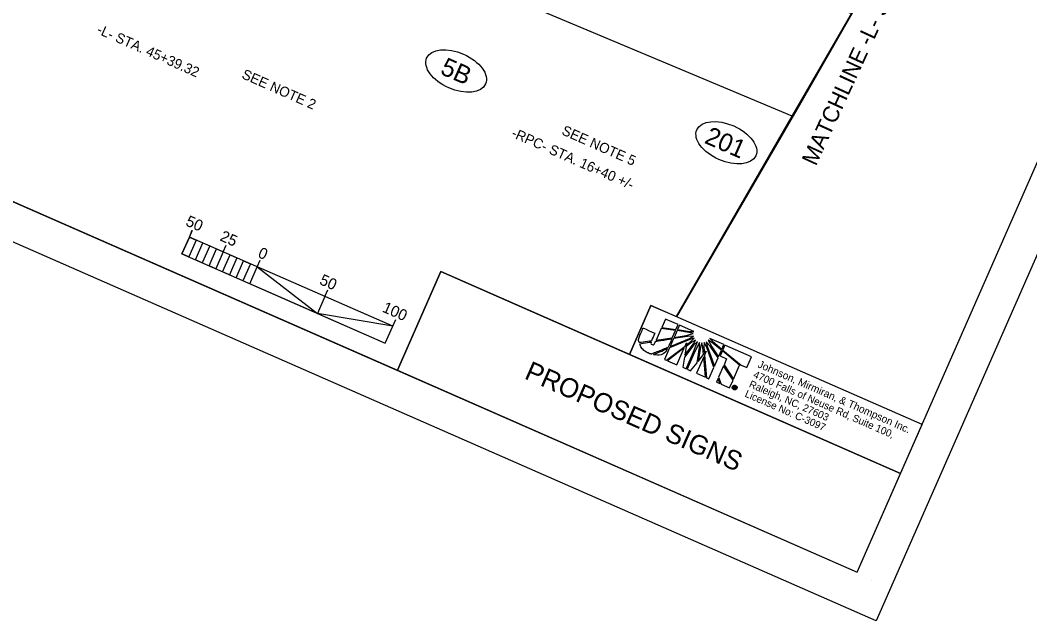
# Model space of a CAD drawing. Extents: x 1639021 to 1641149, y 842052 to 843739.
# Drawn here: x 1639988 to 1640670, y 842052 to 842458 of the extents above; entities that cross this region are included whole.
import ezdxf

# ---------------------------------------------------------------- set-up
doc = ezdxf.new("R2010")
doc.units = 0
for name, color, linetype in [('Default', 7, 'Continuous'), ('Prop Easement Permanent Drainage Utility', 7, 'Continuous'), ('Prop Easement Permanent Drainage Utility Station Offsets', 7, 'Continuous'), ('Prop Horizontal Alignment Tick Small', 7, 'Continuous'), ('Prop Parcel Number Text', 7, 'Continuous'), ('Prop ROW Marker CA CELL', 7, 'Continuous'), ('Prop ROW Marker CELL', 7, 'Continuous'), ('Prop ROW Text', 7, 'Continuous'), ('Prop Sign E Speed Limit XX CELL', 7, 'Continuous'), ('Scratch_Level_2', 7, 'Continuous')]:
    doc.layers.add(name, color=color, linetype=linetype)

msp = doc.modelspace()

# ---------------------------------------------------------------- linework, layer by layer
at = {"layer": 'Default'}
for p, q in [((1640424.27, 842256.42), (1640421.78, 842250.73)), ((1640432.85, 842252.67), (1640424.27, 842256.42)), ((1640431.4, 842249.36), (1640432.85, 842252.67)), ((1640433.76, 842252.32), (1640432.41, 842249.25)), ((1640443.41, 842248.09), (1640433.76, 842252.32)), ((1640421.5, 842250.08), (1640417.99, 842242.09)), ((1640431.13, 842248.73), (1640421.5, 842250.08)), ((1640421.78, 842250.73), (1640431.4, 842249.36)), ((1640428.95, 842243.77), (1640431.13, 842248.73)), ((1640432.12, 842248.58), (1640430.09, 842243.94)), ((1640430.09, 842243.94), (1640438.31, 842245.2)), ((1640440.18, 842247.41), (1640432.12, 842248.58)), ((1640432.41, 842249.25), (1640440.47, 842248.08)), ((1640438.31, 842245.2), (1640443.13, 842246.53)), ((1640443.25, 842244.89), (1640439.26, 842244.66)), ((1640443.13, 842246.53), (1640440.18, 842247.41)), ((1640440.47, 842248.08), (1640443.41, 842248.09)), ((1640440.58, 842243.29), (1640443.25, 842244.89)), ((1640417.99, 842242.09), (1640428.95, 842243.77)), ((1640425.03, 842228.54), (1640437.58, 842238.13)), ((1640440.74, 842242.66), (1640427.02, 842236.94)), ((1640427.42, 842237.84), (1640440.58, 842243.29)), ((1640429.76, 842243.19), (1640427.42, 842237.84)), ((1640439.26, 842244.66), (1640429.76, 842243.19)), ((1640443.56, 842238.88), (1640437.08, 842230.68)), ((1640437.32, 842231.99), (1640443.29, 842239.58)), ((1640437.58, 842238.13), (1640438.57, 842240.39)), ((1640442.03, 842240.68), (1640438.2, 842237.74)), ((1640438.31, 842238.65), (1640441.54, 842241.13)), ((1640438.57, 842240.39), (1640438.31, 842238.65)), ((1640443.79, 842243.42), (1640440.74, 842242.66)), ((1640441.54, 842241.13), (1640443.79, 842243.42)), ((1640444.69, 842242.12), (1640442.03, 842240.68)), ((1640443.29, 842239.58), (1640444.69, 842242.12)), ((1640443.34, 842234.19), (1640445.93, 842241.11)), ((1640445.93, 842241.11), (1640443.56, 842238.88)), ((1640447.35, 842240.49), (1640443.95, 842233.92)), ((1640447.28, 842237.25), (1640447.35, 842240.49)), ((1640448.89, 842240.27), (1640447.97, 842237.41)), ((1640449.59, 842237.37), (1640448.89, 842240.27)), ((1640450.44, 842240.51), (1640450.29, 842237.3)), ((1640451.95, 842237.75), (1640450.44, 842240.51)), ((1640451.9, 842241.1), (1640452.52, 842238.01)), ((1640454.48, 842237.99), (1640451.9, 842241.1)), ((1640452.52, 842238.01), (1640457.4, 842224.59)), ((1640453.23, 842242.1), (1640455.54, 842237.58)), ((1640455.73, 842240.6), (1640453.23, 842242.1)), ((1640463.82, 842239.1), (1640454.33, 842243.3)), ((1640454.33, 842243.3), (1640456.24, 842241.12)), ((1640459.8, 842230.08), (1640454.48, 842237.99)), ((1640462.18, 842235.36), (1640455.73, 842240.6)), ((1640456.24, 842241.12), (1640462.47, 842236.01)), ((1640462.47, 842236.01), (1640463.82, 842239.1)), ((1640464.5, 842238.85), (1640463.05, 842235.54)), ((1640482.53, 842230.95), (1640464.5, 842238.85)), ((1640427.02, 842236.94), (1640423.61, 842229.16)), ((1640437.04, 842236.9), (1640425.69, 842228.24)), ((1640432.09, 842225.44), (1640437.04, 842236.9)), ((1640438.2, 842237.74), (1640437.32, 842231.99)), ((1640438.33, 842222.76), (1640443.34, 842234.19)), ((1640443.95, 842233.92), (1640438.94, 842222.49)), ((1640445.62, 842226.77), (1640447.28, 842237.25)), ((1640447.97, 842237.41), (1640446.4, 842227.77)), ((1640446.4, 842227.77), (1640450.05, 842232.38)), ((1640450.05, 842232.38), (1640449.59, 842237.37)), ((1640450.29, 842237.3), (1640450.63, 842233.09)), ((1640450.63, 842233.09), (1640451.81, 842234.59)), ((1640451.81, 842234.59), (1640450.72, 842232.09)), ((1640450.72, 842232.09), (1640452.12, 842216.66)), ((1640457.01, 842223.7), (1640451.95, 842237.75)), ((1640455.54, 842237.58), (1640460.14, 842230.84)), ((1640460.14, 842230.84), (1640462.18, 842235.36)), ((1640462.76, 842234.87), (1640461.25, 842231.42)), ((1640461.25, 842231.42), (1640465.65, 842229.49)), ((1640462.79, 842234.93), (1640462.76, 842234.87)), ((1640474.41, 842225.31), (1640462.79, 842234.93)), ((1640463.05, 842235.54), (1640463.01, 842235.44)), ((1640463.01, 842235.44), (1640475.46, 842225.24)), ((1640423.61, 842229.16), (1640425.03, 842228.54)), ((1640425.69, 842228.24), (1640432.09, 842225.44)), ((1640437.08, 842230.68), (1640435.98, 842223.79)), ((1640441.32, 842221.45), (1640445.62, 842226.77)), ((1640450.18, 842230.86), (1640445.29, 842219.71)), ((1640451.43, 842217.02), (1640450.18, 842230.86)), ((1640457.4, 842224.59), (1640459.8, 842230.08)), ((1640463.54, 842224.67), (1640460.18, 842217)), ((1640469.97, 842215.18), (1640463.54, 842224.67)), ((1640465.65, 842229.49), (1640463.85, 842225.37)), ((1640463.85, 842225.37), (1640470.26, 842215.85)), ((1640470.26, 842215.85), (1640474.41, 842225.31)), ((1640475.46, 842225.24), (1640479.29, 842223.56)), ((1640479.29, 842223.56), (1640482.53, 842230.95)), ((1640435.98, 842223.79), (1640438.33, 842222.76)), ((1640438.94, 842222.49), (1640441.32, 842221.45)), ((1640445.29, 842219.71), (1640451.43, 842217.02)), ((1640453.64, 842216), (1640457.01, 842223.7)), ((1640452.12, 842216.66), (1640453.64, 842216)), ((1640459.81, 842216.16), (1640458.76, 842213.76)), ((1640458.76, 842213.76), (1640460.98, 842212.78)), ((1640460.98, 842212.78), (1640459.81, 842216.16)), ((1640460.18, 842217), (1640461.83, 842212.41)), ((1640461.83, 842212.41), (1640467.64, 842209.86)), ((1640467.64, 842209.86), (1640469.97, 842215.18)), ((1640470.26, 842209.68), (1640470.83, 842210.99)), ((1640470.83, 842210.99), (1640471.37, 842210.76)), ((1640471.37, 842210.76), (1640471.26, 842210.51)), ((1640471.26, 842210.51), (1640471.37, 842210.76)), ((1640471.37, 842210.76), (1640471.45, 842210.72)), ((1640471.7, 842211.53), (1640471.58, 842211.26)), ((1640471.58, 842211.26), (1640471.7, 842211.53)), ((1640470.55, 842209.55), (1640470.26, 842209.68)), ((1640470.57, 842208.94), (1640470.44, 842208.65)), ((1640470.44, 842208.65), (1640470.57, 842208.94)), ((1640470.45, 842208.65), (1640470.44, 842208.65)), ((1640470.78, 842210.07), (1640470.55, 842209.55)), ((1640470.57, 842208.94), (1640470.58, 842208.93)), ((1640471.02, 842209.96), (1640470.78, 842210.07)), ((1640471.02, 842210.61), (1640470.88, 842210.3)), ((1640470.88, 842210.3), (1640471.12, 842210.2)), ((1640471.26, 842210.51), (1640471.02, 842210.61)), ((1640471.12, 842210.2), (1640471.02, 842209.96)), ((1640471.02, 842209.96), (1640471.12, 842210.2)), ((1640471.03, 842209.96), (1640471.02, 842209.96)), ((1640471.12, 842210.2), (1640471.13, 842210.19)), ((1640471.29, 842210.49), (1640471.26, 842210.51))]:
    msp.add_line(p, q, dxfattribs=at)
msp.add_lwpolyline([(1640399.95, 842232.52), (1640583.09, 842152.07), (1640597.61, 842185.12), (1640414.46, 842265.57)], close=True, dxfattribs=at)
for points in [[(1640421.78, 842250.73), (1640431.4, 842249.36), (1640432.85, 842252.67), (1640424.27, 842256.42), (1640421.78, 842250.73)], [(1640440.47, 842248.08), (1640443.41, 842248.09), (1640433.76, 842252.32), (1640432.41, 842249.25), (1640440.47, 842248.08)], [(1640417.99, 842242.09), (1640428.95, 842243.77), (1640431.13, 842248.73), (1640421.5, 842250.08), (1640417.99, 842242.09)], [(1640429.76, 842243.19), (1640427.42, 842237.84), (1640440.58, 842243.29), (1640443.25, 842244.89), (1640439.26, 842244.66), (1640429.76, 842243.19)], [(1640432.12, 842248.58), (1640430.09, 842243.94), (1640438.31, 842245.2), (1640443.13, 842246.53), (1640440.18, 842247.41), (1640432.12, 842248.58)], [(1640443.79, 842243.42), (1640440.74, 842242.66), (1640427.02, 842236.94), (1640423.61, 842229.16), (1640425.03, 842228.54), (1640437.58, 842238.13), (1640438.57, 842240.39), (1640438.31, 842238.65), (1640441.54, 842241.13), (1640443.79, 842243.42)], [(1640443.56, 842238.88), (1640437.08, 842230.68), (1640435.98, 842223.79), (1640438.33, 842222.76), (1640443.34, 842234.19), (1640445.93, 842241.11), (1640443.56, 842238.88)], [(1640444.69, 842242.12), (1640442.03, 842240.68), (1640438.2, 842237.74), (1640437.32, 842231.99), (1640443.29, 842239.58), (1640444.69, 842242.12)], [(1640447.35, 842240.49), (1640443.95, 842233.92), (1640438.94, 842222.49), (1640441.32, 842221.45), (1640445.62, 842226.77), (1640447.28, 842237.25), (1640447.35, 842240.49)], [(1640448.89, 842240.27), (1640447.97, 842237.41), (1640446.4, 842227.77), (1640450.05, 842232.38), (1640449.59, 842237.37), (1640448.89, 842240.27)], [(1640450.44, 842240.51), (1640450.29, 842237.3), (1640450.63, 842233.09), (1640451.81, 842234.59), (1640450.72, 842232.09), (1640452.12, 842216.66), (1640453.64, 842216), (1640457.01, 842223.7), (1640451.95, 842237.75), (1640450.44, 842240.51)], [(1640451.9, 842241.1), (1640452.52, 842238.01), (1640457.4, 842224.59), (1640459.8, 842230.08), (1640454.48, 842237.99), (1640451.9, 842241.1)], [(1640453.23, 842242.1), (1640455.54, 842237.58), (1640460.14, 842230.84), (1640462.18, 842235.36), (1640455.73, 842240.6), (1640453.23, 842242.1)], [(1640456.24, 842241.12), (1640462.47, 842236.01), (1640463.82, 842239.1), (1640454.33, 842243.3), (1640456.24, 842241.12)], [(1640482.53, 842230.95), (1640464.5, 842238.85), (1640463.05, 842235.54), (1640463.01, 842235.44), (1640475.46, 842225.24), (1640479.29, 842223.56), (1640482.53, 842230.95)], [(1640425.69, 842228.24), (1640432.09, 842225.44), (1640437.04, 842236.9), (1640425.69, 842228.24)], [(1640462.79, 842234.93), (1640462.76, 842234.87), (1640461.25, 842231.42), (1640465.65, 842229.49), (1640463.85, 842225.37), (1640470.26, 842215.85), (1640474.41, 842225.31), (1640462.79, 842234.93)], [(1640445.29, 842219.71), (1640451.43, 842217.02), (1640450.18, 842230.86), (1640445.29, 842219.71)], [(1640463.54, 842224.67), (1640460.18, 842217), (1640461.83, 842212.41), (1640467.64, 842209.86), (1640469.97, 842215.18), (1640463.54, 842224.67), (1640463.54, 842224.67)], [(1640458.76, 842213.76), (1640458.76, 842213.76), (1640460.98, 842212.78), (1640459.81, 842216.16), (1640458.76, 842213.76)], [(1640471.5, 842209.51), (1640471.47, 842209.44), (1640471.46, 842209.38), (1640471.44, 842209.34), (1640471.41, 842209.18), (1640471.14, 842209.3)]]:
    msp.add_lwpolyline(points, dxfattribs=at)
for points, degree in [([(1640417.14, 842246.85), (1640417.14, 842246.85), (1640409.21, 842250.33), (1640409.21, 842250.33), (1640409.21, 842250.33), (1640407.03, 842245.36), (1640407.03, 842245.36), (1640407.03, 842245.36), (1640406.8, 842244.84), (1640406.8, 842244.84), (1640406.12, 842243.28), (1640406.09, 842241.82), (1640406.54, 842240.4), (1640406.54, 842240.4), (1640414.8, 842241.5), (1640414.84, 842241.6), (1640414.84, 842241.6), (1640417.14, 842246.85), (1640417.14, 842246.85)], 3), ([(1640415.24, 842239.16), (1640414.74, 842239.39), (1640414.42, 842239.86), (1640414.65, 842240.89), (1640414.65, 842240.89), (1640406.83, 842239.78), (1640406.83, 842239.78), (1640407.85, 842236.95), (1640410.36, 842234.44), (1640412.92, 842233.32), (1640413.59, 842233.03), (1640414.12, 842232.86), (1640414.89, 842232.69), (1640414.89, 842232.69), (1640426.11, 842237.29), (1640426.11, 842237.29), (1640426.11, 842237.29), (1640428.64, 842243.06), (1640428.64, 842243.06), (1640428.64, 842243.06), (1640417.68, 842241.37), (1640417.68, 842241.37), (1640416.73, 842239.2), (1640415.95, 842238.85), (1640415.24, 842239.16)], 3), ([(1640415.24, 842239.16), (1640414.74, 842239.39), (1640414.42, 842239.86), (1640414.65, 842240.89), (1640414.65, 842240.89), (1640406.83, 842239.78), (1640406.83, 842239.78), (1640407.85, 842236.95), (1640410.36, 842234.44), (1640412.92, 842233.32), (1640413.59, 842233.03), (1640414.12, 842232.86), (1640414.89, 842232.69), (1640414.89, 842232.69), (1640426.11, 842237.29), (1640426.11, 842237.29), (1640426.11, 842237.29), (1640428.64, 842243.06), (1640428.64, 842243.06), (1640428.64, 842243.06), (1640417.68, 842241.37), (1640417.68, 842241.37), (1640416.73, 842239.2), (1640415.95, 842238.85), (1640415.24, 842239.16)], 3), ([(1640425.71, 842236.38), (1640425.71, 842236.38), (1640416.02, 842232.42), (1640416.02, 842232.42), (1640419.64, 842231.79), (1640423.84, 842232.53), (1640425.71, 842236.38)], 3), ([(1640470.44, 842208.65), (1640470.05, 842208.82), (1640469.77, 842209.12), (1640469.6, 842209.53), (1640469.44, 842209.93), (1640469.45, 842210.34), (1640469.62, 842210.74), (1640469.8, 842211.15), (1640470.1, 842211.43), (1640470.5, 842211.57), (1640470.9, 842211.71), (1640471.3, 842211.71), (1640471.7, 842211.53)], 3), ([(1640471.58, 842211.26), (1640471.26, 842211.4), (1640470.94, 842211.41), (1640470.62, 842211.3), (1640470.3, 842211.17), (1640470.05, 842210.94), (1640469.91, 842210.62), (1640469.77, 842210.29), (1640469.76, 842209.96), (1640469.89, 842209.63), (1640470.02, 842209.3), (1640470.25, 842209.08), (1640470.57, 842208.94)], 3), ([(1640470.58, 842208.93), (1640470.9, 842208.79), (1640471.22, 842208.78), (1640471.55, 842208.9), (1640471.87, 842209.03), (1640472.12, 842209.27), (1640472.26, 842209.59), (1640472.4, 842209.91), (1640472.41, 842210.25), (1640472.28, 842210.57), (1640472.15, 842210.89), (1640471.92, 842211.11), (1640471.58, 842211.26)], 3), ([(1640471.45, 842210.72), (1640471.78, 842210.58), (1640471.89, 842210.37), (1640471.78, 842210.11), (1640471.72, 842209.99), (1640471.64, 842209.92), (1640471.5, 842209.89)], 3), ([(1640471.7, 842211.53), (1640472.11, 842211.36), (1640472.39, 842211.06), (1640472.56, 842210.66), (1640472.73, 842210.28), (1640472.72, 842209.87), (1640472.54, 842209.46)], 3), ([(1640472.54, 842209.46), (1640472.37, 842209.06), (1640472.07, 842208.77), (1640471.67, 842208.61), (1640471.27, 842208.46), (1640470.86, 842208.47), (1640470.45, 842208.65)], 3), ([(1640471.23, 842209.81), (1640471.21, 842209.85), (1640471.15, 842209.9), (1640471.03, 842209.96)], 2), ([(1640471.13, 842210.19), (1640471.32, 842210.11), (1640471.44, 842210.13), (1640471.49, 842210.24), (1640471.53, 842210.33), (1640471.47, 842210.42), (1640471.29, 842210.49)], 3), ([(1640471.14, 842209.3), (1640471.13, 842209.38), (1640471.14, 842209.47), (1640471.18, 842209.56), (1640471.23, 842209.68), (1640471.25, 842209.76), (1640471.23, 842209.81)], 3), ([(1640471.5, 842209.89), (1640471.56, 842209.81), (1640471.56, 842209.68), (1640471.5, 842209.51)], 2)]:
    msp.add_open_spline(points, degree=degree, dxfattribs=at)
at = {"layer": 'Prop Easement Permanent Drainage Utility Station Offsets'}
for p, q in [((1640102.72, 842311.83), (1640104.72, 842316.4)), ((1640102.72, 842311.83), (1640097.69, 842300.39)), ((1640240.06, 842251.52), (1640102.72, 842311.83)), ((1640125.6, 842301.77), (1640127.62, 842306.36)), ((1640097.69, 842300.39), (1640235.02, 842240.06)), ((1640134.76, 842297.76), (1640129.74, 842286.31)), ((1640148.49, 842291.72), (1640150.5, 842296.29)), ((1640194.28, 842271.62), (1640196.28, 842276.19)), ((1640194.28, 842271.62), (1640189.25, 842260.18)), ((1640240.06, 842251.52), (1640242.07, 842256.09)), ((1640235.02, 842240.06), (1640240.06, 842251.52))]:
    msp.add_line(p, q, dxfattribs=at)
for points in [[(1640102.72, 842311.83), (1640107.3, 842309.82), (1640102.27, 842298.38), (1640097.69, 842300.39)], [(1640111.87, 842307.81), (1640116.45, 842305.79), (1640111.42, 842294.35), (1640106.85, 842296.35)], [(1640121.02, 842303.78), (1640125.6, 842301.77), (1640120.58, 842290.34), (1640116, 842292.35)], [(1640130.18, 842299.76), (1640134.76, 842297.76), (1640129.74, 842286.31), (1640125.16, 842288.33)], [(1640139.34, 842295.75), (1640143.92, 842293.74), (1640138.89, 842282.28), (1640134.31, 842284.3)], [(1640148.49, 842291.72), (1640189.25, 842260.18), (1640143.47, 842280.27)], [(1640243.29, 842221.76), (1640553.79, 842085.37), (1640583.09, 842152.07), (1640272.59, 842288.47)], [(1640240.06, 842251.52), (1640189.25, 842260.18), (1640235.02, 842240.06)]]:
    msp.add_lwpolyline(points, close=True, dxfattribs=at)
at = {"layer": 'Prop Horizontal Alignment Tick Small'}
msp.add_lwpolyline([(1639448.15, 842571.05), (1640243.29, 842221.76), (1640272.59, 842288.47), (1640399.95, 842232.52), (1640414.46, 842265.57), (1640431.68, 842258.01), (1640509.88, 842393.53), (1640578.69, 842512.77), (1640588.08, 842537.98), (1640589.14, 842540.82), (1640590.2, 842543.68), (1640594.14, 842554.24), (1640597.32, 842562.78), (1640602.19, 842575.88), (1640617.73, 842617.59), (1640629.05, 842742.44), (1640442.75, 843074.22), (1640333.27, 843069.27), (1640224.04, 843351.63), (1640060.58, 843430.64), (1640037.67, 843446.57), (1639929.48, 843492.21)], dxfattribs=at)
msp.add_lwpolyline([(1640509.88, 842393.53), (1640258.27, 842499.49), (1639851.27, 842640.65), (1639497.72, 842648.98), (1639258.85, 842745.98), (1639284.06, 842802.84), (1639323.71, 842812.08), (1639324.89, 842810.47), (1639332.61, 842801.05), (1640071.73, 842651.02), (1640549.92, 842462.92)], close=True, dxfattribs=at)
at = {"layer": 'Prop Parcel Number Text'}
for p, q in [((1640102.73, 842311.84), (1640104.74, 842316.41)), ((1640125.62, 842301.78), (1640127.63, 842306.35)), ((1640194.29, 842271.63), (1640196.3, 842276.2)), ((1640240.07, 842251.51), (1640242.08, 842256.1))]:
    msp.add_line(p, q, dxfattribs=at)
at = {"layer": 'Prop ROW Marker CA CELL'}
msp.add_lwpolyline([(1640432.05, 842257.85), (1640513.21, 842398.08), (1640578.69, 842512.77), (1640598.78, 842566.73), (1640617.73, 842617.59), (1640629.05, 842742.44), (1640614.97, 842767.52), (1640442.75, 843074.22)], dxfattribs=at)
at = {"layer": 'Prop ROW Marker CELL'}
for p, q in [((1640563.35, 842079.47), (1640563.35, 842079.47)), ((1640566.6, 842052.4), (1640566.6, 842052.4))]:
    msp.add_line(p, q, dxfattribs=at)
msp.add_lwpolyline([(1640976.52, 843047.68), (1639603.84, 843650.67), (1639181.11, 842688.36), (1640553.79, 842085.37)], close=True, dxfattribs=at)
at = {"layer": 'Prop ROW Text'}
msp.add_lwpolyline([(1639463.57, 843738.43), (1641009.03, 843059.54), (1640566.63, 842052.42), (1639021.17, 842731.32)], close=True, dxfattribs=at)
at = {"layer": 'Prop Sign E Speed Limit XX CELL'}
for centre in [(1640282.9, 842424.06), (1640465.43, 842375.56)]:
    msp.add_ellipse(centre, major_axis=(-19.9, 8.74), ratio=0.571429, dxfattribs=at)
at = {"layer": 'Scratch_Level_2'}
msp.add_lwpolyline([(1639284.06, 842802.84), (1639323.71, 842812.08), (1639324.89, 842810.47), (1639315.52, 842798.54), (1639318.23, 842795.35), (1639494.05, 842768.28), (1639987.22, 842668.18), (1640071.73, 842651.02), (1640171.87, 842611.63), (1640533.86, 842469.24), (1640549.92, 842462.92), (1640509.88, 842393.53), (1640280.71, 842490.04), (1640234.72, 842507.66), (1639851.27, 842640.65), (1639497.72, 842648.98), (1639263.95, 842757.5), (1639284.06, 842802.84)], dxfattribs=at)

# ---------------------------------------------------------------- texts
at = {"layer": 'Default'}
for s, height, rotation, p in [('-L- STA. 45+39.32', 6.7709, 336.1242, (1640039.68, 842449.71)), ('SEE NOTE 2', 6.771, 336.1242, (1640137.58, 842419.4)), ('-RPC- STA. 16+40 +/-', 6.7709, 336.1242, (1640319.71, 842379.75)), ('SEE NOTE 5', 6.771, 336.1242, (1640353.65, 842381.41)), ('PROPOSED SIGNS', 13, 336.28496, (1640328.36, 842216.42)), ('Johnson, Mirmiran, & Thompson Inc.', 5.1112, 336.28496, (1640486.17, 842223.97)), ('4700 Falls of Neuse Rd, Suite 100, ', 4.9652, 336.28496, (1640483.15, 842217.11)), ('Raleigh, NC, 27603', 4.9652, 336.28496, (1640480.3, 842210.61)), ('License No: C-3097', 4.9652, 336.28496, (1640477.45, 842204.12))]:
    msp.add_text(s, height=height, rotation=rotation, dxfattribs=at).set_placement(p)
at = {"layer": 'Prop Easement Permanent Drainage Utility'}
msp.add_text('MATCHLINE -L- STA. 51+00.00 (SEE SIGN-14)', height=11, rotation=65.29, dxfattribs=at).set_placement((1640525.9, 842359.34))
at = {"layer": 'Prop Easement Permanent Drainage Utility Station Offsets'}
for s, p in [('50', (1640099.62, 842319.9)), ('25', (1640122.83, 842309.7)), ('0', (1640148.45, 842298.45)), ('50', (1640190.05, 842280.18)), ('100', (1640232.48, 842261.55))]:
    msp.add_text(s, height=7.5, rotation=336.28973, dxfattribs=at).set_placement(p)
at = {"layer": 'Prop Sign E Speed Limit XX CELL'}
for s, p in [('5B', (1640271.44, 842422.39)), ('201', (1640449.97, 842375.65))]:
    msp.add_text(s, height=12.271, rotation=336.28496, dxfattribs=at).set_placement(p)

doc.saveas('drawing.dxf')
